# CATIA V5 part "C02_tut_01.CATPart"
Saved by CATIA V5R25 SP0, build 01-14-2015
Part number: Part1
Bounding box of the stored display mesh (mm): x 0 to 0, y 0 to 120, z 0 to 59.999
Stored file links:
  E:\ashutosh\Academics\Catia\CATIA V5-6R2013_partfiles\Tutorials_ver_2\C02_tut_01.CATPart
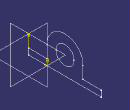
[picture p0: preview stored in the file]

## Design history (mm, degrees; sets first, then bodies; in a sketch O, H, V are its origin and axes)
Body1 (main body)
  Sketch1 on yz-plane, origin (0, 0, 0), H (0, 1, 0), V (0, 0, 1)
    line L1 (0, 0) -> (120, 0)
    line L2 (120, 0) -> (120, 10)
    line L3 (120, 10) -> (90, 10)
    line L4 (90, 10) -> (90, 30)
    arc A1 centre (60, 30) radius 30 from (90, 30) to (30, 30) ccw
    line L5 (30, 30) -> (30, 10)
    point P7 (30, 10)
    line L6 (30, 10) -> (0, 10)
    line L7 (0, 10) -> (0, 0)
    circle A2 centre (60, 30) radius 15
    radius A2 = 15
    horizontal: L1 H, L3 H, L6 H
    vertical: L2 V, L4 V, L7 V
    tangency: A1 L1, A1 L4, L5 A1
    coincidence: P7 L3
